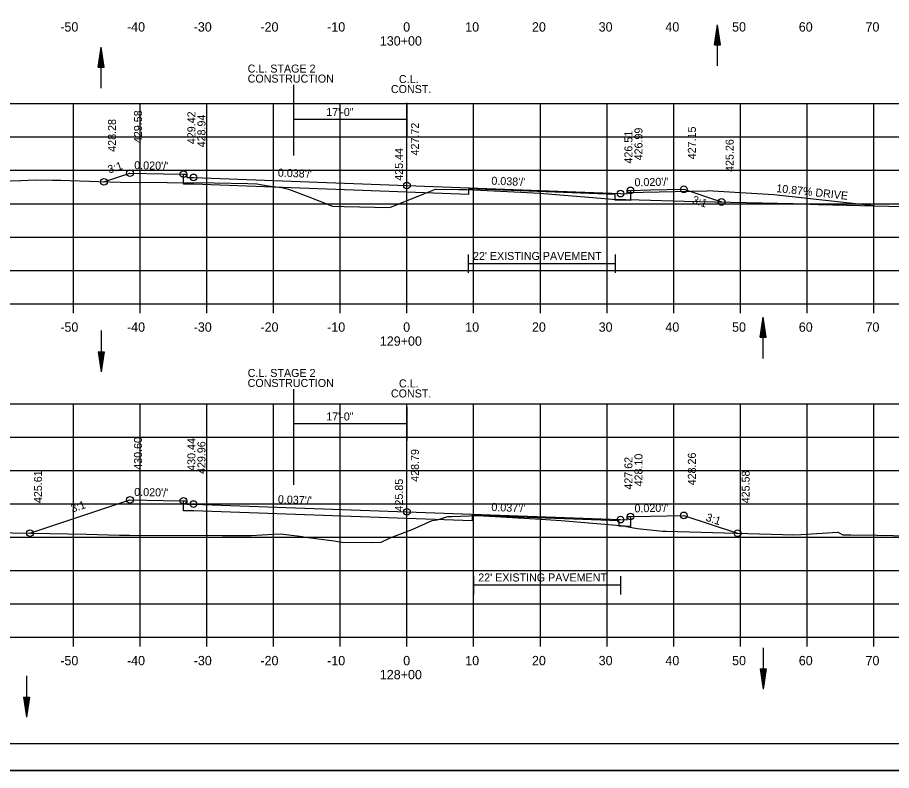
# Model space of a CAD drawing. Extents: x 1538688 to 1540766, y 656250 to 671912.
# Drawn here: x 1538799.8 to 1538930.8, y 660391.3 to 660504.2 of the extents above; entities that cross this region are included whole.
import ezdxf

# ---------------------------------------------------------------- set-up
doc = ezdxf.new("R2010")
doc.units = 0
for name, color, linetype in [('15', 7, 'Continuous'), ('16', 7, 'Continuous'), ('18', 7, 'Continuous'), ('20', 7, 'Continuous'), ('22', 7, 'Continuous'), ('26', 7, 'Continuous'), ('39', 7, 'Continuous'), ('41', 7, 'Continuous'), ('42', 7, 'Continuous'), ('7', 7, 'Continuous'), ('Borings', 7, 'Continuous'), ('Default', 7, 'Continuous'), ('Horizontal Alignment', 7, 'Continuous'), ('RipRap', 7, 'Continuous'), ('Wall Heights', 7, 'Continuous')]:
    doc.layers.add(name, color=color, linetype=linetype)

msp = doc.modelspace()

# ---------------------------------------------------------------- linework, layer by layer
at = {"layer": '15'}
for p, q in [((1538904.3, 660500.13), (1538904.75, 660503.13)), ((1538904.37, 660500.13), (1538904.75, 660502.63)), ((1538904.45, 660500.13), (1538904.75, 660502.11)), ((1538905.2, 660500.13), (1538904.75, 660503.13)), ((1538905.12, 660500.13), (1538904.75, 660502.63)), ((1538905.04, 660500.13), (1538904.75, 660502.11)), ((1538904.52, 660500.13), (1538904.75, 660501.61)), ((1538904.6, 660500.13), (1538904.75, 660501.1)), ((1538904.97, 660500.13), (1538904.75, 660501.61)), ((1538904.89, 660500.13), (1538904.75, 660501.1)), ((1538811.89, 660496.78), (1538812.34, 660499.78)), ((1538812.79, 660496.78), (1538812.34, 660499.78)), ((1538904.3, 660500.13), (1538905.2, 660500.13)), ((1538904.68, 660500.13), (1538904.75, 660500.6)), ((1538904.82, 660500.13), (1538904.75, 660500.6)), ((1538811.97, 660496.78), (1538812.34, 660499.28)), ((1538812.04, 660496.78), (1538812.34, 660498.77)), ((1538812.12, 660496.78), (1538812.34, 660498.27)), ((1538812.72, 660496.78), (1538812.34, 660499.28)), ((1538812.64, 660496.78), (1538812.34, 660498.77)), ((1538812.56, 660496.78), (1538812.34, 660498.27)), ((1538812.19, 660496.78), (1538812.34, 660497.76)), ((1538812.27, 660496.78), (1538812.34, 660497.26)), ((1538812.49, 660496.78), (1538812.34, 660497.76)), ((1538812.41, 660496.78), (1538812.34, 660497.26)), ((1538811.89, 660496.78), (1538812.79, 660496.78)), ((1538911.11, 660456.28), (1538911.56, 660459.28)), ((1538912.01, 660456.28), (1538911.56, 660459.28)), ((1538911.19, 660456.28), (1538911.56, 660458.78)), ((1538911.26, 660456.28), (1538911.56, 660458.26)), ((1538911.34, 660456.28), (1538911.56, 660457.76)), ((1538911.94, 660456.28), (1538911.56, 660458.78)), ((1538911.86, 660456.28), (1538911.56, 660458.26)), ((1538911.78, 660456.28), (1538911.56, 660457.76)), ((1538911.11, 660456.28), (1538912.01, 660456.28)), ((1538911.42, 660456.28), (1538911.56, 660457.26)), ((1538911.49, 660456.28), (1538911.56, 660456.75)), ((1538911.71, 660456.28), (1538911.56, 660457.26)), ((1538911.63, 660456.28), (1538911.56, 660456.75)), ((1538811.89, 660454.1), (1538812.34, 660451.1)), ((1538811.89, 660454.1), (1538812.79, 660454.1)), ((1538811.97, 660454.1), (1538812.34, 660451.6)), ((1538812.04, 660454.1), (1538812.34, 660452.12)), ((1538812.12, 660454.1), (1538812.34, 660452.62)), ((1538812.19, 660454.1), (1538812.34, 660453.12)), ((1538812.27, 660454.1), (1538812.34, 660453.63)), ((1538812.79, 660454.1), (1538812.34, 660451.1)), ((1538812.49, 660454.1), (1538812.34, 660453.12)), ((1538812.64, 660454.1), (1538812.34, 660452.12)), ((1538812.72, 660454.1), (1538812.34, 660451.6)), ((1538812.56, 660454.1), (1538812.34, 660452.62)), ((1538812.41, 660454.1), (1538812.34, 660453.63)), ((1538911.11, 660406.54), (1538911.56, 660403.54)), ((1538911.11, 660406.54), (1538912.01, 660406.54)), ((1538911.19, 660406.54), (1538911.56, 660404.04)), ((1538911.26, 660406.54), (1538911.56, 660404.55)), ((1538911.34, 660406.54), (1538911.56, 660405.05)), ((1538911.42, 660406.54), (1538911.56, 660405.56)), ((1538911.49, 660406.54), (1538911.56, 660406.06)), ((1538912.01, 660406.54), (1538911.56, 660403.54)), ((1538911.71, 660406.54), (1538911.56, 660405.56)), ((1538911.86, 660406.54), (1538911.56, 660404.55)), ((1538911.94, 660406.54), (1538911.56, 660404.04)), ((1538911.78, 660406.54), (1538911.56, 660405.05)), ((1538911.63, 660406.54), (1538911.56, 660406.06)), ((1538800.73, 660402.3), (1538801.18, 660399.3)), ((1538800.73, 660402.3), (1538801.63, 660402.3)), ((1538800.8, 660402.3), (1538801.18, 660399.8)), ((1538800.88, 660402.3), (1538801.18, 660400.31)), ((1538800.95, 660402.3), (1538801.18, 660400.81)), ((1538801.03, 660402.3), (1538801.18, 660401.32)), ((1538801.1, 660402.3), (1538801.18, 660401.82)), ((1538801.63, 660402.3), (1538801.18, 660399.3)), ((1538801.32, 660402.3), (1538801.18, 660401.32)), ((1538801.47, 660402.3), (1538801.18, 660400.31)), ((1538801.55, 660402.3), (1538801.18, 660399.8)), ((1538801.4, 660402.3), (1538801.18, 660400.81)), ((1538801.25, 660402.3), (1538801.18, 660401.82))]:
    msp.add_line(p, q, dxfattribs=at)
at = {"layer": '16'}
for p, q in [((1538891.18, 660477.96), (1538903.17, 660478.2)), ((1538913.16, 660477.6), (1538903.17, 660478.2)), ((1538928.18, 660475.97), (1538913.16, 660477.6))]:
    msp.add_line(p, q, dxfattribs=at)
at = {"layer": '18'}
for points in [[(1538797.15, 660479.69), (1538800.3, 660479.79), (1538802.51, 660479.89), (1538805.05, 660479.82), (1538806.3, 660479.82), (1538811.94, 660479.6), (1538815.2, 660479.52), (1538829.31, 660479.4), (1538834.31, 660479.31), (1538835.7, 660479.25), (1538837.37, 660478.98), (1538839.4, 660478.71), (1538840.45, 660478.46), (1538843.48, 660477.33), (1538847.01, 660475.91), (1538848.76, 660475.89), (1538855.63, 660475.73), (1538860.7, 660477.75), (1538862.48, 660478.48), (1538865.91, 660478.44), (1538867.16, 660478.44), (1538875.27, 660478), (1538878.04, 660477.85), (1538886.67, 660477.18), (1538889.01, 660476.99), (1538893, 660476.86), (1538899.76, 660476.69), (1538916.06, 660476.31), (1538919.85, 660476.16), (1538936.73, 660475.77)], [(1538796.24, 660427.01), (1538810.17, 660426.75), (1538815.12, 660426.58), (1538816.62, 660426.59), (1538830.47, 660426.55), (1538834.84, 660426.57), (1538838.12, 660426.76), (1538839.24, 660426.78), (1538842.12, 660426.46), (1538843.37, 660426.27), (1538847.26, 660425.77), (1538848.44, 660425.56), (1538852.97, 660425.52), (1538854.31, 660425.55), (1538855.66, 660426.19), (1538858.95, 660427.45), (1538861.97, 660428.79), (1538862.73, 660428.9), (1538864.32, 660429.41), (1538864.91, 660429.42), (1538868.8, 660429.55), (1538878.31, 660428.98), (1538879.76, 660428.89), (1538881.31, 660428.78), (1538890.8, 660427.99), (1538891.11, 660427.92), (1538892.7, 660427.62), (1538896.53, 660427.19), (1538897.05, 660427.18), (1538914.53, 660426.69), (1538916, 660426.65), (1538917.25, 660426.71), (1538922.78, 660427.06), (1538922.97, 660426.96), (1538923.52, 660426.66), (1538923.84, 660426.66), (1538924.73, 660426.66), (1538928.63, 660426.6), (1538956.16, 660426.07)]]:
    msp.add_lwpolyline(points, dxfattribs=at)
at = {"layer": '20'}
for points in [[(1538812.77, 660479.58), (1538816.67, 660480.88), (1538821.67, 660480.78), (1538824.67, 660480.72), (1538825.17, 660480.72), (1538825.18, 660480.22), (1538826.18, 660480.24), (1538858.18, 660479.03), (1538890.18, 660477.81), (1538891.18, 660477.79), (1538891.19, 660478.29), (1538891.69, 660478.29), (1538894.69, 660478.35), (1538899.69, 660478.45), (1538905.35, 660476.56)], [(1538801.68, 660426.91), (1538816.67, 660431.91), (1538821.67, 660431.81), (1538824.67, 660431.75), (1538825.17, 660431.75), (1538825.18, 660431.25), (1538826.18, 660431.27), (1538858.18, 660430.1), (1538890.18, 660428.93), (1538891.18, 660428.91), (1538891.19, 660429.41), (1538891.69, 660429.41), (1538894.69, 660429.47), (1538899.69, 660429.57), (1538907.75, 660426.88)]]:
    msp.add_lwpolyline(points, dxfattribs=at)
at = {"layer": '22'}
for p, q in [((1538718.18, 660491.3), (1538998.18, 660491.3)), ((1538808.18, 660461.3), (1538808.18, 660491.3)), ((1538818.18, 660461.3), (1538818.18, 660491.3)), ((1538828.18, 660461.3), (1538828.18, 660491.3)), ((1538838.18, 660461.3), (1538838.18, 660491.3)), ((1538848.18, 660461.3), (1538848.18, 660491.3)), ((1538858.18, 660461.3), (1538858.18, 660491.3)), ((1538868.18, 660461.3), (1538868.18, 660491.3)), ((1538878.18, 660461.3), (1538878.18, 660491.3)), ((1538888.18, 660461.3), (1538888.18, 660491.3)), ((1538898.18, 660461.3), (1538898.18, 660491.3)), ((1538908.18, 660461.3), (1538908.18, 660491.3)), ((1538918.18, 660461.3), (1538918.18, 660491.3)), ((1538928.18, 660461.3), (1538928.18, 660491.3)), ((1538718.18, 660486.3), (1538998.18, 660486.3)), ((1538718.18, 660481.3), (1538998.18, 660481.3)), ((1538718.18, 660476.3), (1538998.18, 660476.3)), ((1538718.18, 660471.3), (1538998.18, 660471.3)), ((1538718.18, 660466.3), (1538998.18, 660466.3)), ((1538718.18, 660461.3), (1538998.18, 660461.3)), ((1538718.18, 660446.3), (1538998.18, 660446.3)), ((1538808.18, 660411.3), (1538808.18, 660446.3)), ((1538818.18, 660411.3), (1538818.18, 660446.3)), ((1538828.18, 660411.3), (1538828.18, 660446.3)), ((1538838.18, 660411.3), (1538838.18, 660446.3)), ((1538848.18, 660411.3), (1538848.18, 660446.3)), ((1538858.18, 660411.3), (1538858.18, 660446.3)), ((1538868.18, 660411.3), (1538868.18, 660446.3)), ((1538878.18, 660411.3), (1538878.18, 660446.3)), ((1538888.18, 660411.3), (1538888.18, 660446.3)), ((1538898.18, 660411.3), (1538898.18, 660446.3)), ((1538908.18, 660411.3), (1538908.18, 660446.3)), ((1538918.18, 660411.3), (1538918.18, 660446.3)), ((1538928.18, 660411.3), (1538928.18, 660446.3)), ((1538718.18, 660441.3), (1538998.18, 660441.3)), ((1538718.18, 660436.3), (1538998.18, 660436.3)), ((1538718.18, 660431.3), (1538998.18, 660431.3)), ((1538718.18, 660426.3), (1538998.18, 660426.3)), ((1538718.18, 660421.3), (1538998.18, 660421.3)), ((1538718.18, 660416.3), (1538998.18, 660416.3)), ((1538718.18, 660411.3), (1538998.18, 660411.3))]:
    msp.add_line(p, q, dxfattribs=at)
at = {"layer": '26'}
msp.add_line((1538687.78, 660391.32), (1539021.11, 660391.32), dxfattribs=at)
msp.add_lwpolyline([(1538687.77, 660604.66), (1539021.11, 660604.66), (1539021.11, 660391.32), (1538687.77, 660391.32)], close=True, dxfattribs=at)
for centre in [(1538816.67, 660480.88), (1538824.67, 660480.72), (1538812.77, 660479.58), (1538826.18, 660480.24), (1538858.18, 660479.03), (1538891.69, 660478.29), (1538899.69, 660478.45), (1538890.18, 660477.81), (1538905.35, 660476.56), (1538816.67, 660431.91), (1538824.67, 660431.75), (1538826.18, 660431.27), (1538858.18, 660430.1), (1538899.69, 660429.57), (1538890.18, 660428.93), (1538891.69, 660429.41), (1538801.68, 660426.91), (1538907.75, 660426.88)]:
    msp.add_circle(centre, 0.5, dxfattribs=at)
at = {"layer": '39'}
for p, q in [((1538904.75, 660496.94), (1538904.75, 660503.13)), ((1538812.34, 660493.6), (1538812.34, 660499.78)), ((1538911.56, 660453.09), (1538911.56, 660459.28)), ((1538812.34, 660457.29), (1538812.34, 660451.1)), ((1538911.56, 660409.72), (1538911.56, 660403.54)), ((1538801.18, 660405.49), (1538801.18, 660399.3))]:
    msp.add_line(p, q, dxfattribs=at)
at = {"layer": '7'}
for p, q in [((1538867.38, 660468.68), (1538867.38, 660465.93)), ((1538889.38, 660468.68), (1538889.38, 660465.93)), ((1538889.38, 660467.3), (1538867.38, 660467.3)), ((1538868.17, 660420.48), (1538868.17, 660417.73)), ((1538890.17, 660420.48), (1538890.17, 660417.73)), ((1538890.17, 660419.1), (1538868.17, 660419.1))]:
    msp.add_line(p, q, dxfattribs=at)
at = {"layer": 'Borings'}
for p, q in [((1538718.18, 660461.3), (1538998.18, 660461.3)), ((1538808.18, 660459.9), (1538808.18, 660461.3)), ((1538818.18, 660459.9), (1538818.18, 660461.3)), ((1538828.18, 660459.9), (1538828.18, 660461.3)), ((1538838.18, 660459.9), (1538838.18, 660461.3)), ((1538848.18, 660459.9), (1538848.18, 660461.3)), ((1538858.18, 660459.9), (1538858.18, 660461.3)), ((1538868.18, 660459.9), (1538868.18, 660461.3)), ((1538878.18, 660459.9), (1538878.18, 660461.3)), ((1538888.18, 660459.9), (1538888.18, 660461.3)), ((1538898.18, 660459.9), (1538898.18, 660461.3)), ((1538908.18, 660459.9), (1538908.18, 660461.3)), ((1538918.18, 660459.9), (1538918.18, 660461.3)), ((1538928.18, 660459.9), (1538928.18, 660461.3)), ((1538718.18, 660411.3), (1538998.18, 660411.3)), ((1538808.18, 660409.9), (1538808.18, 660411.3)), ((1538818.18, 660409.9), (1538818.18, 660411.3)), ((1538828.18, 660409.9), (1538828.18, 660411.3)), ((1538838.18, 660409.9), (1538838.18, 660411.3)), ((1538848.18, 660409.9), (1538848.18, 660411.3)), ((1538858.18, 660409.9), (1538858.18, 660411.3)), ((1538868.18, 660409.9), (1538868.18, 660411.3)), ((1538878.18, 660409.9), (1538878.18, 660411.3)), ((1538888.18, 660409.9), (1538888.18, 660411.3)), ((1538898.18, 660409.9), (1538898.18, 660411.3)), ((1538908.18, 660409.9), (1538908.18, 660411.3)), ((1538918.18, 660409.9), (1538918.18, 660411.3)), ((1538928.18, 660409.9), (1538928.18, 660411.3))]:
    msp.add_line(p, q, dxfattribs=at)
at = {"layer": 'Default'}
for p, q in [((1538841.17, 660494.11), (1538841.17, 660483.52)), ((1538858.18, 660491.43), (1538858.18, 660486.43)), ((1538858.18, 660488.93), (1538841.17, 660488.93)), ((1538841.17, 660448.48), (1538841.17, 660434.13)), ((1538858.18, 660445.8), (1538858.18, 660440.8)), ((1538858.18, 660443.3), (1538841.17, 660443.3))]:
    msp.add_line(p, q, dxfattribs=at)
at = {"layer": 'RipRap'}
msp.add_line((1539016.36, 660395.3), (1538700.18, 660395.3), dxfattribs=at)
at = {"layer": 'Wall Heights'}
for points in [[(1538891.69, 660478.29), (1538891.69, 660476.79), (1538890.18, 660476.81), (1538889.39, 660476.84), (1538889.39, 660477.67), (1538867.39, 660478.51), (1538867.39, 660477.68), (1538858.18, 660478.03), (1538826.18, 660479.24), (1538824.67, 660479.22), (1538824.67, 660480.72)], [(1538891.69, 660429.41), (1538891.69, 660427.91), (1538890.18, 660427.93), (1538889.97, 660427.93), (1538889.97, 660428.77), (1538867.97, 660429.57), (1538867.97, 660428.74), (1538858.18, 660429.1), (1538826.18, 660430.27), (1538824.67, 660430.25), (1538824.67, 660431.75)]]:
    msp.add_lwpolyline(points, dxfattribs=at)

# ---------------------------------------------------------------- texts
at = {"layer": '16'}
msp.add_text('10.87% DRIVE', height=1.2, rotation=353.7979, dxfattribs=at).set_placement((1538913.5, 660478.04))
at = {"layer": '41'}
for s, p in [('429.58', (1538818.47, 660485.38)), ('429.42', (1538826.47, 660485.22)), ('428.94', (1538827.98, 660484.74)), ('428.28', (1538814.57, 660484.08)), ('427.72', (1538859.98, 660483.53)), ('427.15', (1538901.49, 660482.95)), ('426.51', (1538891.98, 660482.31)), ('426.99', (1538893.49, 660482.79)), ('425.26', (1538907.15, 660481.06)), ('425.44', (1538857.58, 660479.74)), ('430.60', (1538818.47, 660436.41)), ('430.44', (1538826.47, 660436.25)), ('429.96', (1538827.98, 660435.77)), ('428.79', (1538859.98, 660434.6)), ('427.62', (1538891.98, 660433.43)), ('428.10', (1538893.49, 660433.91)), ('428.26', (1538901.49, 660434.07)), ('425.61', (1538803.48, 660431.41)), ('425.58', (1538909.55, 660431.38)), ('425.85', (1538857.58, 660430.15))]:
    msp.add_text(s, height=1.2, rotation=90, dxfattribs=at).set_placement(p)
at = {"layer": '42'}
for s, rotation, p in [('3:1', 18.4349, (1538813.56, 660480.81)), ("0.020'/'", 358.8542, (1538817.3, 660481.47)), ("0.038'/'", 357.8238, (1538838.82, 660480.36)), ("0.038'/'", 357.8238, (1538870.82, 660479.15)), ("0.020'/'", 1.1458, (1538892.3, 660478.9)), ('3:1', 341.5651, (1538900.83, 660476.4)), ("0.020'/'", 358.8542, (1538817.3, 660432.49)), ('3:1', 18.4349, (1538808.02, 660429.98)), ("0.037'/'", 357.907, (1538838.82, 660431.4)), ("0.037'/'", 357.907, (1538870.82, 660430.23)), ("0.020'/'", 1.1458, (1538892.3, 660430.02)), ('3:1', 341.5651, (1538902.88, 660428.8))]:
    msp.add_text(s, height=1.2, rotation=rotation, dxfattribs=at).set_placement(p)
at = {"layer": '7'}
for p in [(1538868.08, 660467.86), (1538868.87, 660419.66)]:
    msp.add_text("22' EXISTING PAVEMENT", height=1.2, dxfattribs=at).set_placement(p)
at = {"layer": 'Default'}
for s, p in [('C.L. STAGE 2', (1538834.31, 660495.95)), ('CONSTRUCTION', (1538834.3, 660494.45)), ('C.L.', (1538856.98, 660494.38)), ('CONST.', (1538855.78, 660492.88)), ('17\'-0"', (1538846.09, 660489.44)), ('C.L. STAGE 2', (1538834.31, 660450.32)), ('CONSTRUCTION', (1538834.3, 660448.82)), ('C.L.', (1538856.98, 660448.75)), ('CONST.', (1538855.78, 660447.25)), ('17\'-0"', (1538846.09, 660443.8))]:
    msp.add_text(s, height=1.2, dxfattribs=at).set_placement(p)
at = {"layer": 'Horizontal Alignment'}
for s, p in [('-50', (1538806.22, 660502.1)), ('-40', (1538816.22, 660502.1)), ('-30', (1538826.22, 660502.1)), ('-20', (1538836.22, 660502.1)), ('-10', (1538846.22, 660502.1)), ('0', (1538857.62, 660502.1)), ('10', (1538866.92, 660502.1)), ('20', (1538876.92, 660502.1)), ('30', (1538886.92, 660502.1)), ('40', (1538896.92, 660502.1)), ('50', (1538906.92, 660502.1)), ('60', (1538916.92, 660502.1)), ('70', (1538926.92, 660502.1)), ('130+00', (1538854.12, 660500)), ('-50', (1538806.22, 660457.1)), ('-40', (1538816.22, 660457.1)), ('-30', (1538826.22, 660457.1)), ('-20', (1538836.22, 660457.1)), ('-10', (1538846.22, 660457.1)), ('0', (1538857.62, 660457.1)), ('10', (1538866.92, 660457.1)), ('20', (1538876.92, 660457.1)), ('30', (1538886.92, 660457.1)), ('40', (1538896.92, 660457.1)), ('50', (1538906.92, 660457.1)), ('60', (1538916.92, 660457.1)), ('70', (1538926.92, 660457.1)), ('129+00', (1538854.12, 660455)), ('-50', (1538806.22, 660407.1)), ('-40', (1538816.22, 660407.1)), ('-30', (1538826.22, 660407.1)), ('-20', (1538836.22, 660407.1)), ('-10', (1538846.22, 660407.1)), ('0', (1538857.62, 660407.1)), ('10', (1538866.92, 660407.1)), ('20', (1538876.92, 660407.1)), ('30', (1538886.92, 660407.1)), ('40', (1538896.92, 660407.1)), ('50', (1538906.92, 660407.1)), ('60', (1538916.92, 660407.1)), ('70', (1538926.92, 660407.1)), ('128+00', (1538854.12, 660405))]:
    msp.add_text(s, height=1.4, dxfattribs=at).set_placement(p)

doc.saveas('drawing.dxf')
